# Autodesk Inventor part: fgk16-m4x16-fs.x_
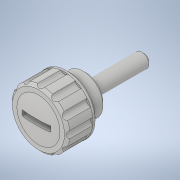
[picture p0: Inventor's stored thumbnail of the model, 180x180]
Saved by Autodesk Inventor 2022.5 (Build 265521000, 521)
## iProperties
Created: 2021-08
Part Number: fgk16-m4x16-fs.x_
Material: 一般
Document SubType Name: Modeling
Designer: ImaoCorp
Density: 1 g/cm^3
Appearance: 既定
Sending System: SOLIDWORKS 2019-2019304
MC: AMD64
MC_MODEL: Intel64 Family 6 Model 60 Stepping 3, GenuineIntel
OS: Windows_NT
FRU: Parasolid Version 31.0, build 290,  9- 1-2019
FORMAT: text
GUISE: transmit
KEY: fgk16-m4x16-fs
FILE: fgk16-m4x16-fs.x_t
DATE: Wed Aug 11 15:02:27 2021
Author: ImaoCorp
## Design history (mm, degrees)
feature "Base1"
node "ソリッド1"
